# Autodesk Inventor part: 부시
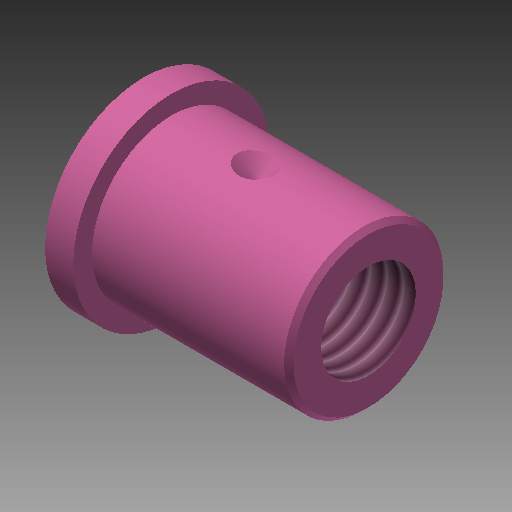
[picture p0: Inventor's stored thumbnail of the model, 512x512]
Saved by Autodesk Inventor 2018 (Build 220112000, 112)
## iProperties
Created: 2019-04
Part Number: 부시
Material: 강철, 연강
Document SubType Name: Modeling
Designer: mduedu
Density: 1 g/cm^3
Appearance: Pink
Author: mduedu
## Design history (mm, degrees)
sketch "스케치1"
  geometry: L1 (0, 0)-(3, 0); L2 (3, 0)-(3, 10.5); L3 (3, 10.5)-(0, 10.5); L4 (0, 10.5)-(0, 0); L5 (3, 0)-(24, 0); L6 (24, 0)-(24, 8.5); L7 (24, 8.5)-(3, 8.5); L8 (3, 8.5)-(3, 0)
  constraints: 16 end point, 4 parallel, 2 horizontal, 2 perpendicular
  dimensions: "d0" = 3 distance of L2.end L3.end; "d2" = 24 distance between parallel lines of L6 L4; "d3" = 17 diameter of L7 L5; "d4" = 21 diameter of L3 L1
revolve "회전1" sketch "스케치1" stored, may be unused: angle "d5" = 90 deg
sketch "스케치2"
  geometry: L1 (3, 8.5)-(24, 8.5) reference; L2 (12, 8.5)-(12, 6.5); L3 (12, 6.5)-(14, 8.5); L4 (0, -10.5)-(0, 10.5) reference; 1 further point
  constraints: 4 end point, 2 point on line, 1 perpendicular
  dimensions: "d6" = 12 distance from line of L2.start L4; "d7" = 2 distance of L2.start L3.end; "d8" = 45 deg angle of L3 L2
revolve "회전2" sketch "스케치2" stored, may be unused: angle "d9" = 90 deg
hole "구멍1" diameter "d12" = 10.106; stored, may be unused: countersink angle "d16" = 90 deg, drill point angle "d18" = 118 deg; dims "d10" = 10, "d11" = 10, "d13" = 39, "d14" = 4, "d15" = 2, "d17" = 8
chamfer "모따기1" distance "d19" = 0.5; stored, may be unused: second distance "d20" = 2, angle "d21" = 45 deg
node "작업점1"
  node "작업 평면1"
  node "작업축1"
node "솔리드1"
